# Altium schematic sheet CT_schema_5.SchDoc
size 368 x 309 mm
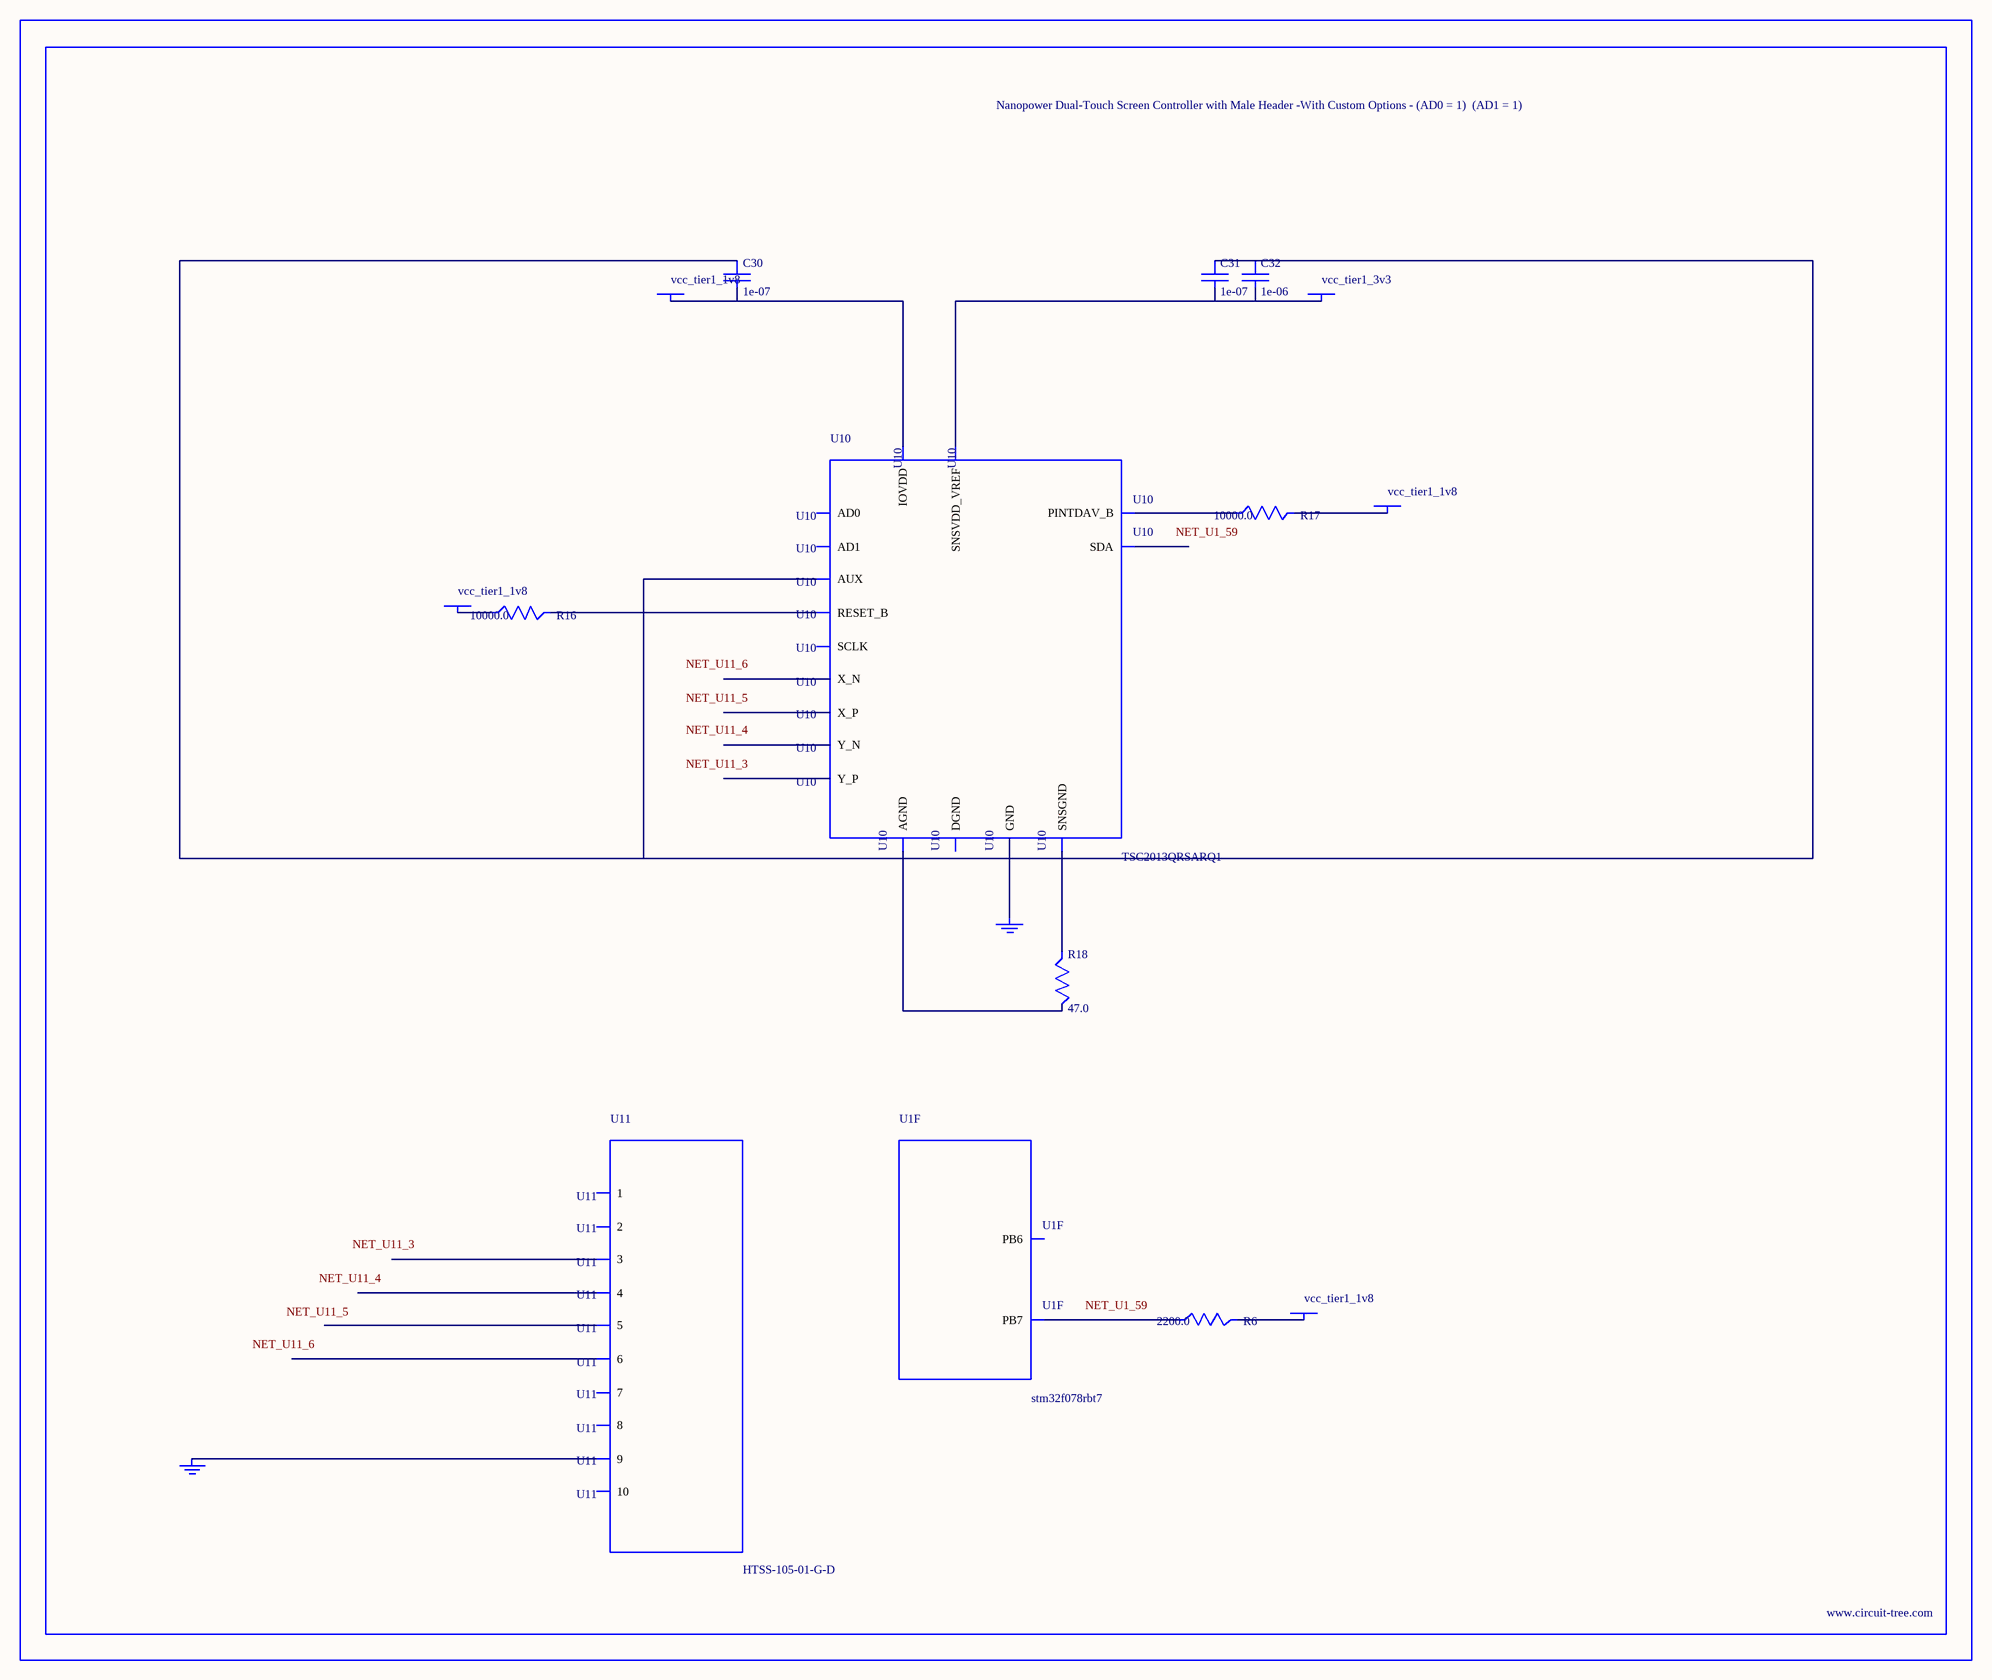
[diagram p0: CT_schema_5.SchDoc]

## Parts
BORDER4  (no value)
C30  1e-07  [C0402]
C31  1e-07  [C0402]
C32  1e-06  [C0603]
GND_INSTANCE_4_0  (no value)
GND_INSTANCE_4_1  (no value)
POWER_INSTANCE_4_0  vcc_tier1_1v8
POWER_INSTANCE_4_1  vcc_tier1_1v8
POWER_INSTANCE_4_2  vcc_tier1_1v8
POWER_INSTANCE_4_3  vcc_tier1_3v3
POWER_INSTANCE_4_4  vcc_tier1_1v8
R6  2200.0  [R0603]
R16  10000.0  [R0603]
R17  10000.0  [R0603]
R18  47.0  [R0603]
U1  stm32f078rbt7  [LQFP64]  (part F of 7)
U10  TSC2013QRSARQ1  [QFN65P400X400X100-17N]
U11  HTSS-105-01-G-D  [HTSS-105-01-G-D]

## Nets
NetC30_1: C30.1 C31.1 C32.1 R18.1 R18.2 U10.8(AUX) U10.9(AGND) U10.15(SNSGND)
NetC30_2: C30.2 POWER_INSTANCE_4_2.0(PWR) U10.7(IOVDD)
NetC31_2: C31.2 C32.2 POWER_INSTANCE_4_3.0(PWR) U10.10(SNSVDD_VREF)
NetGND_INSTANCE_4_0_0: GND_INSTANCE_4_0.0(GND) U10.17(GND)
NetGND_INSTANCE_4_1_0: GND_INSTANCE_4_1.0(GND) U11.9
NetPOWER_INSTANCE_4_0_0: POWER_INSTANCE_4_0.0(PWR) R17.2
NetPOWER_INSTANCE_4_1_0: POWER_INSTANCE_4_1.0(PWR) R16.1
NetPOWER_INSTANCE_4_4_0: POWER_INSTANCE_4_4.0(PWR) R6.2
NetR6_1: R6.1 U1.59(PB7)
NetR16_2: R16.2 U10.5(RESET_B)
NetR17_1: R17.1 U10.4(PINTDAV_B)

Not connected (* = marked no-connect by the designer): U1 58(PB6); U10 1(SDA) 2(SCLK) 3(AD1) 6(DGND) 11(X_P) 12(Y_P) 13(X_N) 14(Y_N) 16(AD0); U11 1 2 3 4 5 6 7 8 10

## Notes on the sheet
- Labels drawn without touching a wire or pin: NET_U1_59, NET_U11_3, NET_U11_4, NET_U11_5, NET_U11_6

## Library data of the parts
BORDER4 = BORDER_PAGE4
C30 C31 = C0402C104K3RACTU
C32 = C0603C105K3RACTU
GND_INSTANCE_4_0 GND_INSTANCE_4_1 = GND
POWER_INSTANCE_4_0-POWER_INSTANCE_4_4 = PWR
R6 = RC0603JR-072K2L
R16 R17 = RC0603JR-0710KL
R18 = RC0603JR-0747RL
